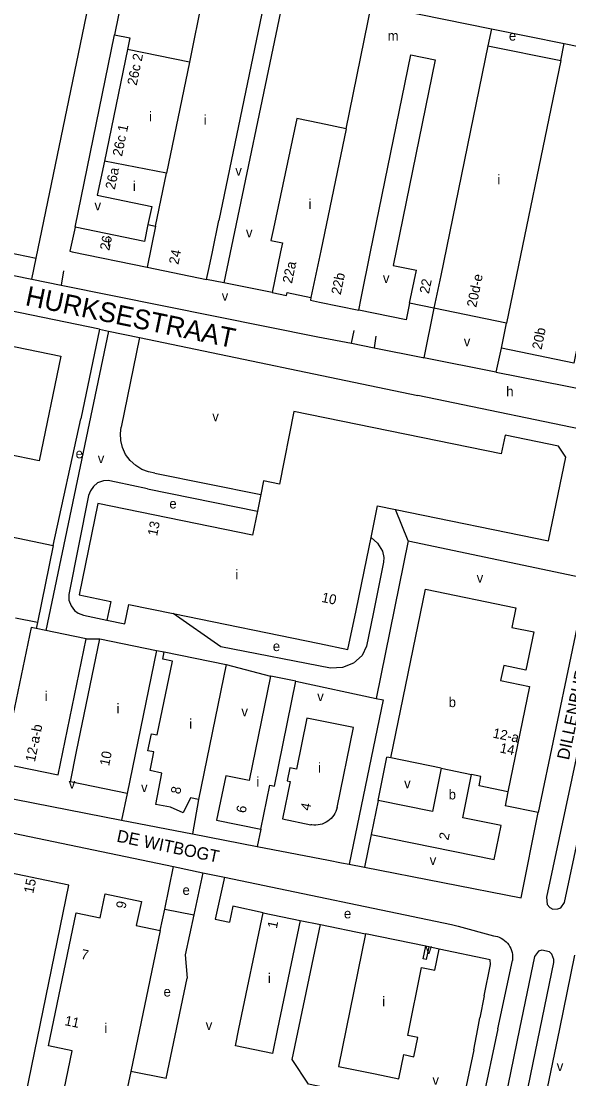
# Model space of a CAD drawing. Extents: x 157699 to 159683, y 381451 to 383293.
# Drawn here: x 158378.5 to 158601.6, y 382412.9 to 382844 of the extents above; entities that cross this region are included whole.
import ezdxf

# ---------------------------------------------------------------- set-up
doc = ezdxf.new("R2010")
doc.units = 0
for name, color, linetype in [('BLT_Basislijn', 7, 'Continuous'), ('BLT_Bebouwing', 7, 'Continuous'), ('BLT_Centroide', 7, 'Continuous'), ('BLT_Huisnummer', 7, 'Continuous'), ('BLT_Huisnummer_reeks', 7, 'Continuous'), ('BLT_Onderverdeling_panden', 7, 'Continuous'), ('BLT_Plantopo', 7, 'Continuous'), ('BLT_Straatnaam', 7, 'Continuous'), ('BLT_Straatnaam_hoofdweg', 7, 'Continuous'), ('BLT_Vlakafsluiter', 7, 'Continuous')]:
    doc.layers.add(name, color=color, linetype=linetype)

msp = doc.modelspace()

# ---------------------------------------------------------------- linework, layer by layer
at = {"layer": 'BLT_Basislijn'}
for p, q in [((158384.61, 382747.34), (158410.62, 382872.97)), ((158486.16, 382857.78), (158461.09, 382737.28)), ((158400.47, 382760.04), (158416.52, 382838.4)), ((158570.05, 382840.89), (158599.68, 382834.8)), ((158286.11, 382757.88), (158382.94, 382738.83)), ((158382.94, 382738.83), (158384.61, 382747.34)), ((158461.09, 382737.28), (158454.07, 382738.66)), ((158410.45, 382718.37), (158328.18, 382735.5)), ((158480.77, 382733.42), (158461.09, 382737.28)), ((158546.65, 382727.02), (158542.51, 382706.8)), ((158414.12, 382717.61), (158388.52, 382595.62)), ((158410.45, 382718.37), (158402.83, 382681.84)), ((158410.45, 382718.37), (158414.12, 382717.61)), ((158414.12, 382717.61), (158426.69, 382714.99)), ((158426.69, 382714.99), (158419.28, 382678.53)), ((158426.69, 382714.99), (158540.03, 382691.39)), ((158572.04, 382700.92), (158574.14, 382710.64)), ((158572.04, 382700.92), (158609.92, 382693.48)), ((158391.62, 382630.22), (158402.83, 382681.84)), ((158432.98, 382659.8), (158476.16, 382651.06)), ((158430, 382653.4), (158474.78, 382644.32)), ((158536.17, 382632.21), (158530.94, 382644.98)), ((158536.17, 382632.21), (158523.05, 382567.93)), ((158536.17, 382632.21), (158609.02, 382616.76)), ((158609.02, 382616.76), (158589.07, 382521.46)), ((158385.16, 382598.84), (158384.66, 382596.42)), ((158405.05, 382592.21), (158410.51, 382592.23)), ((158433.61, 382587.41), (158436.83, 382586.86)), ((158462.01, 382581.71), (158480.03, 382577.02)), ((158480.03, 382577.02), (158480.23, 382577)), ((158490.43, 382574.91), (158523.05, 382567.93)), ((158525.97, 382567.3), (158512.07, 382500.35)), ((158523.05, 382567.93), (158525.97, 382567.3)), ((158523.92, 382526.35), (158527.51, 382543.97)), ((158529.04, 382543.66), (158527.51, 382543.97)), ((158362.62, 382529.42), (158419.43, 382518.37)), ((158421.7, 382529.18), (158419.43, 382518.37)), ((158450.75, 382526.74), (158448.29, 382512.76)), ((158576.78, 382529.93), (158575.61, 382524.22)), ((158589.07, 382521.46), (158575.61, 382524.22)), ((158419.43, 382518.37), (158448.29, 382512.76)), ((158362.15, 382515.73), (158440.61, 382499.4)), ((158476.17, 382514.65), (158474.68, 382507.63)), ((158448.29, 382512.76), (158474.68, 382507.63)), ((158521.08, 382512.45), (158518.37, 382499.13)), ((158474.68, 382507.63), (158503.67, 382501.99)), ((158503.67, 382501.99), (158509, 382500.95)), ((158509, 382500.95), (158512.07, 382500.35)), ((158436.99, 382482.07), (158440.61, 382499.4)), ((158440.61, 382499.4), (158452.53, 382496.92)), ((158452.53, 382496.92), (158448.82, 382479.68)), ((158452.53, 382496.92), (158461.32, 382495.09)), ((158512.07, 382500.35), (158518.37, 382499.13)), ((158461.32, 382495.09), (158457.61, 382477.91)), ((158461.32, 382495.09), (158553.82, 382475.83)), ((158435.18, 382473.39), (158436.99, 382482.07)), ((158492.18, 382477.45), (158500.45, 382475.74)), ((158500.45, 382475.74), (158518.8, 382471.96)), ((158553.82, 382475.83), (158556.45, 382475.11)), ((158556.45, 382475.11), (158570.84, 382471.19)), ((158572.61, 382433.33), (158578.58, 382461.13)), ((158567.16, 382446.79), (158565.36, 382437.79)), ((158572.61, 382433.33), (158554.1, 382344.5)), ((158562.84, 382424.73), (158558.87, 382405.41)), ((158437.58, 382412.99), (158423.23, 382415.87))]:
    msp.add_line(p, q, dxfattribs=at)
for points in [[(158395.8, 382742.21), (158394.76, 382736.37)], [(158394.76, 382736.37), (158499.39, 382715.24), (158513.12, 382712.75)], [(158536.73, 382729.06), (158535.33, 382722.24), (158515.99, 382726.22)], [(158513.12, 382712.75), (158514.13, 382717.95)], [(158523.04, 382715.55), (158522.33, 382710.79)], [(158522.33, 382710.79), (158542.18, 382706.86), (158542.51, 382706.8)], [(158572.04, 382700.92), (158571.83, 382700.96), (158542.51, 382706.8)], [(158617.29, 382675.37), (158540.03, 382691.39)], [(158432.98, 382659.8), (158430.36, 382660.29), (158427.71, 382661.29), (158425.17, 382662.84), (158422.92, 382664.9), (158421.09, 382667.39), (158419.81, 382670.17), (158419.1, 382673.05), (158418.95, 382675.89), (158419.28, 382678.53)], [(158430, 382653.4), (158417.18, 382656.06), (158413.93, 382656.73), (158412.04, 382656.62), (158409.67, 382655.75), (158408.06, 382654.36), (158406.74, 382652.51), (158405.94, 382650.65), (158397.91, 382610.35), (158397.97, 382608), (158398.83, 382605.74), (158400.23, 382603.81), (158401.73, 382602.62), (158403.87, 382601.88), (158413.43, 382599.83)], [(158627.93, 382652.23), (158626.35, 382647.12), (158616.3, 382599.72), (158615.3, 382593.85), (158592.52, 382487), (158592.73, 382483.96), (158593.85, 382482.78), (158595.1, 382482.02), (158597.16, 382482.16), (158598.35, 382482.54), (158599.78, 382484.77), (158632.13, 382636.44)], [(158521.02, 382633.56), (158523.62, 382631.18), (158525.67, 382627.9), (158526.2, 382625.32), (158526.09, 382623.49), (158521.84, 382602.36)], [(158521.84, 382602.36), (158519.12, 382589.3), (158517.38, 382585.46), (158513.89, 382582.31), (158509.35, 382580.57), (158504.46, 382580.22), (158459.91, 382588.93), (158440.4, 382602.54)], [(158518.37, 382499.13), (158582.21, 382486.71), (158589.07, 382521.46)], [(158436.99, 382482.07), (158448.82, 382479.68)], [(158448.82, 382479.68), (158445.31, 382463.42), (158446.12, 382453.94)], [(158477.13, 382480.6), (158464.7, 382483.21), (158463.35, 382476.76)], [(158457.61, 382477.91), (158463.35, 382476.76)], [(158533.71, 382395.49), (158535.16, 382402.41), (158495.57, 382410.69), (158488.96, 382420.8), (158500.45, 382475.74)], [(158570.84, 382471.19), (158571.67, 382471.06), (158572.48, 382470.86), (158573.26, 382470.58), (158574.02, 382470.22), (158574.74, 382469.79), (158575.42, 382469.3), (158576.04, 382468.74), (158576.61, 382468.13), (158577.12, 382467.47), (158577.56, 382466.76), (158577.94, 382466.01), (158578.24, 382465.23), (158578.46, 382464.42), (158578.61, 382463.6), (158578.68, 382462.76), (158578.66, 382461.92), (158578.58, 382461.13)], [(158544.52, 382466.66), (158543.36, 382466.96)], [(158567.16, 382446.79), (158569.71, 382459.44), (158569.6, 382461.44), (158548.76, 382465.79)], [(158589.92, 382433.33), (158595.48, 382460.27), (158595.51, 382461.5), (158594.69, 382463.74), (158593.67, 382464.66), (158590.55, 382465.32), (158589.18, 382464.95), (158587.53, 382462.82), (158581.51, 382433.33), (158566.21, 382358.35), (158566.28, 382354.58), (158568.34, 382352.66), (158571.2, 382352.4), (158572.77, 382353.27), (158573.3, 382354.15), (158574, 382356.06), (158578.99, 382380.49), (158589.92, 382433.33)], [(158583.87, 382342.43), (158582.82, 382342.64), (158580.69, 382344.1), (158580.25, 382344.99), (158580.69, 382351.18), (158592.27, 382405.81), (158597.9, 382433.33), (158604.02, 382463.33)], [(158437.58, 382412.99), (158446.12, 382453.94)], [(158562.84, 382424.73), (158564.49, 382433.33), (158565.36, 382437.79)]]:
    msp.add_lwpolyline(points, dxfattribs=at)
at = {"layer": 'BLT_Bebouwing'}
for p, q in [((158479.05, 382859.19), (158459.06, 382762.75)), ((158510.92, 382800.12), (158521.2, 382850.79)), ((158521.2, 382850.79), (158570.05, 382840.89)), ((158570.05, 382840.89), (158568.65, 382833.95)), ((158568.65, 382833.95), (158598.29, 382827.93)), ((158598.29, 382827.93), (158599.68, 382834.8)), ((158421.85, 382832.36), (158412.41, 382786.89)), ((158431.69, 382768.41), (158430.18, 382761.08)), ((158400.47, 382760.04), (158398.42, 382750.17)), ((158429.8, 382743.68), (158454.07, 382738.66)), ((158576.26, 382720.94), (158546.65, 382727.02)), ((158574.14, 382710.64), (158576.26, 382720.94)), ((158477.28, 382656.56), (158476.16, 382651.06)), ((158476.16, 382651.06), (158474.78, 382644.32)), ((158521.02, 382633.56), (158523.64, 382646.48)), ((158523.64, 382646.48), (158530.94, 382644.98)), ((158352.94, 382638.28), (158391.62, 382630.22)), ((158384.66, 382596.42), (158382.54, 382596.85)), ((158388.52, 382595.62), (158384.66, 382596.42)), ((158395.83, 382594.11), (158388.52, 382595.62)), ((158405.05, 382592.21), (158395.83, 382594.11)), ((158410.51, 382592.23), (158433.61, 382587.41)), ((158433.61, 382587.41), (158421.7, 382529.18)), ((158436.83, 382586.86), (158462.01, 382581.71)), ((158462.01, 382581.71), (158450.75, 382526.74)), ((158480.04, 382577.04), (158480.03, 382577.02)), ((158480.23, 382577), (158480.04, 382577.04)), ((158490.43, 382574.91), (158480.23, 382577)), ((158507.23, 382523.44), (158513.91, 382556.08)), ((158389.72, 382426.3), (158400.94, 382480.49)), ((158477.13, 382480.6), (158492.18, 382477.45)), ((158435.18, 382473.39), (158423.23, 382415.87)), ((158543.36, 382466.96), (158518.8, 382471.96)), ((158480.83, 382423.25), (158465.78, 382426.4)), ((158423.23, 382415.87), (158414.43, 382375.34)), ((158507.79, 382417.95), (158522.67, 382414.92))]:
    msp.add_line(p, q, dxfattribs=at)
for points in [[(158423.18, 382870.75), (158419.98, 382855.29), (158416.52, 382838.4)], [(158416.52, 382838.4), (158422.82, 382837.11), (158421.85, 382832.36)], [(158599.68, 382834.8), (158638.09, 382827.01), (158642.99, 382826.01)], [(158515.99, 382726.22), (158516.99, 382731.12), (158520.86, 382750), (158537.25, 382830.18), (158547.18, 382828.15), (158530.09, 382744.37), (158539.48, 382742.44)], [(158510.92, 382800.12), (158500, 382802.33), (158490.76, 382804.25), (158481.31, 382759.44), (158480.27, 382754.55), (158484.9, 382753.59)], [(158412.41, 382786.89), (158409.54, 382772.99), (158431.69, 382768.41)], [(158634.53, 382784.28), (158620.4, 382787.15), (158612.86, 382750), (158603.62, 382704.58), (158574.14, 382710.64)], [(158430.18, 382761.08), (158428.75, 382754.19), (158400.47, 382760.04)], [(158454.07, 382738.66), (158455.09, 382743.55), (158456.42, 382750), (158459.06, 382762.75)], [(158484.9, 382753.59), (158484.16, 382750), (158480.77, 382733.42)], [(158398.42, 382750.17), (158399.24, 382750), (158429.8, 382743.68)], [(158536.73, 382729.06), (158539.48, 382742.44)], [(158480.77, 382733.42), (158486.65, 382732.22), (158486.89, 382733.4), (158496.56, 382731.39)], [(158496.56, 382731.39), (158496.33, 382730.24), (158500, 382729.49), (158515.99, 382726.22)], [(158546.65, 382727.02), (158536.73, 382729.06)], [(158325.37, 382721.64), (158394.7, 382707.39), (158385.9, 382664.78), (158359.46, 382670.22), (158352.94, 382638.28)], [(158530.94, 382644.98), (158593.32, 382632.17), (158600.33, 382666.26), (158597.41, 382670.76), (158575.61, 382675.25), (158574.05, 382667.63), (158489.61, 382684.94), (158483.74, 382655.23), (158477.28, 382656.56)], [(158474.78, 382644.32), (158472.78, 382634.5), (158409.75, 382647.36), (158402.09, 382610.15), (158415.01, 382607.48), (158413.43, 382599.83)], [(158391.62, 382630.22), (158385.16, 382598.84)], [(158514.91, 382603.79), (158519.28, 382624.99), (158521.02, 382633.56)], [(158529.04, 382543.66), (158543.16, 382612.44), (158579.97, 382604.87)], [(158413.43, 382599.83), (158420.71, 382598.33), (158422.33, 382606.24), (158440.4, 382602.54)], [(158579.97, 382604.87), (158578.34, 382596.85), (158587.26, 382595.02), (158584.08, 382579.5), (158575.14, 382581.34), (158573.78, 382575.19)], [(158385.16, 382598.84), (158376.2, 382600.68)], [(158440.4, 382602.54), (158500, 382590.32), (158511.64, 382587.92), (158514.91, 382603.79)], [(158382.54, 382596.85), (158371.13, 382541.39), (158393.66, 382536.76), (158405.05, 382592.21)], [(158421.7, 382529.18), (158398.59, 382533.96), (158401.11, 382546.25), (158410.51, 382592.23)], [(158450.75, 382526.74), (158447.46, 382527.38), (158444.54, 382521.31), (158439.37, 382523.56), (158433.34, 382524.7), (158435.81, 382537.41), (158431.01, 382538.5), (158431.96, 382543.33), (158432.54, 382546.14), (158430.18, 382546.62), (158431.6, 382553.52), (158433.96, 382553.03), (158440.13, 382583.09), (158436.23, 382583.88), (158436.83, 382586.86)], [(158480.03, 382577.02), (158471.34, 382534.44), (158461.86, 382536.37), (158458.15, 382518.36), (158476.17, 382514.65)], [(158476.17, 382514.65), (158479.86, 382532.57), (158481.67, 382532.21), (158490.43, 382574.91)], [(158573.78, 382575.19), (158585.55, 382572.77), (158576.78, 382529.93)], [(158513.91, 382556.08), (158494.93, 382559.93), (158490.64, 382539.13), (158487.98, 382539.69), (158486.88, 382534.3), (158488.07, 382534.05), (158484.9, 382518.84), (158496.54, 382516.44)], [(158549.6, 382539.47), (158529.04, 382543.66)], [(158521.08, 382512.45), (158571.17, 382502.24), (158574.01, 382516.13), (158558.39, 382519.31), (158561.98, 382536.94)], [(158549.6, 382539.47), (158546, 382521.84), (158523.92, 382526.35)], [(158565.78, 382536.16), (158561.98, 382536.94)], [(158576.78, 382529.93), (158565, 382532.35), (158565.78, 382536.16)], [(158507.23, 382523.44), (158506.99, 382522.61), (158506.68, 382521.81), (158506.3, 382521.04), (158505.84, 382520.3), (158505.33, 382519.62), (158504.74, 382518.99), (158504.11, 382518.41), (158503.42, 382517.89), (158502.69, 382517.44), (158501.91, 382517.06), (158501.11, 382516.75), (158500.28, 382516.52), (158499.44, 382516.37), (158498.58, 382516.29), (158497.72, 382516.3), (158496.86, 382516.39), (158496.54, 382516.44)], [(158523.92, 382526.35), (158521.08, 382512.45)], [(158398.01, 382491.76), (158367.33, 382498.18), (158365.12, 382486.84), (158373.94, 382485.02), (158368.21, 382457.15)], [(158379.37, 382401), (158398.01, 382491.76)], [(158400.94, 382480.49), (158410.7, 382478.47), (158412.68, 382488.28), (158427.49, 382485.2), (158425.42, 382475.43), (158435.18, 382473.39)], [(158465.78, 382426.4), (158467.23, 382433.33), (158477.13, 382480.6)], [(158492.18, 382477.45), (158482.94, 382433.33), (158480.83, 382423.25)], [(158518.8, 382471.96), (158510.93, 382433.33), (158507.79, 382417.95)], [(158544.52, 382466.66), (158543.49, 382461.57), (158542.31, 382461.81), (158543.36, 382466.96)], [(158548.76, 382465.79), (158544.52, 382466.66)], [(158522.67, 382414.92), (158532.36, 382412.94), (158534.36, 382422.76), (158538.49, 382421.92), (158540.07, 382429.71), (158535.95, 382430.55), (158541.59, 382458.27), (158546.32, 382457.31), (158547, 382457.17), (158548.76, 382465.79)], [(158390.2, 382380.31), (158399.27, 382424.37), (158389.72, 382426.3)]]:
    msp.add_lwpolyline(points, dxfattribs=at)
at = {"layer": 'BLT_Onderverdeling_panden'}
for p, q in [((158454.49, 382864.27), (158447.07, 382827.2)), ((158568.65, 382833.95), (158549.39, 382740.34)), ((158447.07, 382827.2), (158421.85, 382832.36)), ((158447.07, 382827.2), (158437.73, 382782.01)), ((158598.29, 382827.93), (158576.26, 382720.94)), ((158510.92, 382800.12), (158500.54, 382750.39)), ((158437.73, 382782.01), (158412.41, 382786.89)), ((158433.27, 382760.44), (158437.73, 382782.01)), ((158433.27, 382760.44), (158429.8, 382743.68)), ((158430.18, 382761.08), (158433.27, 382760.44)), ((158500.54, 382750.39), (158496.56, 382731.39)), ((158549.39, 382740.34), (158546.65, 382727.02)), ((158549.6, 382539.47), (158561.98, 382536.94))]:
    msp.add_line(p, q, dxfattribs=at)
at = {"layer": 'BLT_Plantopo'}
msp.add_line((158344.3, 382755.69), (158384.61, 382747.34), dxfattribs=at)
at = {"layer": 'BLT_Vlakafsluiter'}
for p, q in [((158382.94, 382738.83), (158394.76, 382736.37)), ((158513.12, 382712.75), (158522.33, 382710.79))]:
    msp.add_line(p, q, dxfattribs=at)

# ---------------------------------------------------------------- texts
at = {"layer": 'BLT_Centroide'}
for s, p in [('m', (158527.79, 382836)), ('e', (158577.17, 382836.03)), ('i', (158430.59, 382803.09)), ('i', (158452.88, 382801.75)), ('v', (158465.75, 382781.02)), ('i', (158572.47, 382777.44)), ('i', (158424.06, 382774.78)), ('v', (158408.4, 382766.85)), ('i', (158495.59, 382767.42)), ('i', (158413.59, 382752.19)), ('v', (158470.09, 382755.86)), ('v', (158525.86, 382737.26)), ('v', (158460.21, 382730.01)), ('v', (158558.79, 382711.49)), ('h', (158576.09, 382691.09)), ('v', (158456.37, 382680.93)), ('e', (158400.71, 382665.79)), ('v', (158409.72, 382663.82)), ('e', (158438.88, 382645.34)), ('i', (158465.8, 382616.41)), ('v', (158564.04, 382615.13)), ('e', (158481.03, 382587.23)), ('i', (158388.11, 382566.88)), ('v', (158499.1, 382566.84)), ('i', (158417.36, 382561.8)), ('b', (158552.64, 382564.4)), ('v', (158468.22, 382560.66)), ('i', (158446.98, 382555.59)), ('i', (158499.41, 382537.7)), ('i', (158474.3, 382531.97)), ('v', (158397.91, 382531.19)), ('v', (158427.36, 382529.76)), ('v', (158534.5, 382531.36)), ('b', (158552.64, 382526.78)), ('v', (158544.91, 382500.05)), ('e', (158444.25, 382487.84)), ('e', (158509.98, 382478.29)), ('v', (158543.18, 382463.8)), ('i', (158478.98, 382451.92)), ('e', (158436.53, 382446.44)), ('i', (158525.58, 382442.44)), ('i', (158412.45, 382431.58)), ('v', (158453.69, 382432.82)), ('v', (158596.65, 382416.09)), ('v', (158546.03, 382410.5))]:
    msp.add_text(s, height=4, dxfattribs=at).set_placement(p)
at = {"layer": 'BLT_Huisnummer'}
for s, rotation, p in [('26a', 78.3139, (158416.66, 382775.11)), ('26', 78.3191, (158414.41, 382750.28)), ('24', 78.3112, (158442.54, 382744.57)), ('22a', 78.444, (158488.81, 382736.85)), ('20b', 78.5, (158590.45, 382709.89)), ('10', 78.4525, (158414.32, 382540.18)), ('8', 78.4525, (158443.27, 382528.7)), ('6', 78.3535, (158469.93, 382520.99)), ('4', 78.248, (158496.1, 382522)), ('2', 78.3797, (158552.51, 382509.96)), ('15', 78.386, (158383.45, 382488.23)), ('1', 78.4874, (158482.65, 382473.95))]:
    msp.add_text(s, height=4, rotation=rotation, dxfattribs=at).set_placement(p)
at = {"layer": 'BLT_Huisnummer_reeks'}
for s, rotation, p in [('26c 2', 78.3139, (158425.56, 382817.52)), ('26c 1', 78.3139, (158419.58, 382788.63)), ('22b', 78.3754, (158508.66, 382732.24)), ('22', 78.3754, (158544.59, 382732.66)), ('20d-e', 78.3619, (158563.86, 382727.1)), ('13', 78.3543, (158433.86, 382633.91)), ('10', 348.3797, (158500.66, 382607.3)), ('12-a-b', 78.3877, (158384.12, 382541.82)), ('12-a', 348.4698, (158570.37, 382552)), ('14', 348.3797, (158573.23, 382545.95)), ('9', 78.277, (158420.98, 382481.99)), ('7', 348.3046, (158402.64, 382461.9)), ('11', 348.277, (158396.01, 382434.82))]:
    msp.add_text(s, height=4, rotation=rotation, dxfattribs=at).set_placement(p)
at = {"layer": 'BLT_Straatnaam'}
for s, rotation, p in [('DILLENBURGSTRAAT', 78.2074, (158601.58, 382542.58)), ('DE WITBOGT', 348.186, (158417.16, 382509.62))]:
    msp.add_text(s, height=5, rotation=rotation, dxfattribs=at).set_placement(p)
at = {"layer": 'BLT_Straatnaam_hoofdweg'}
msp.add_text('HURKSESTRAAT', height=8, rotation=348.3051, dxfattribs=at).set_placement((158379.84, 382728.27))

doc.saveas('drawing.dxf')
